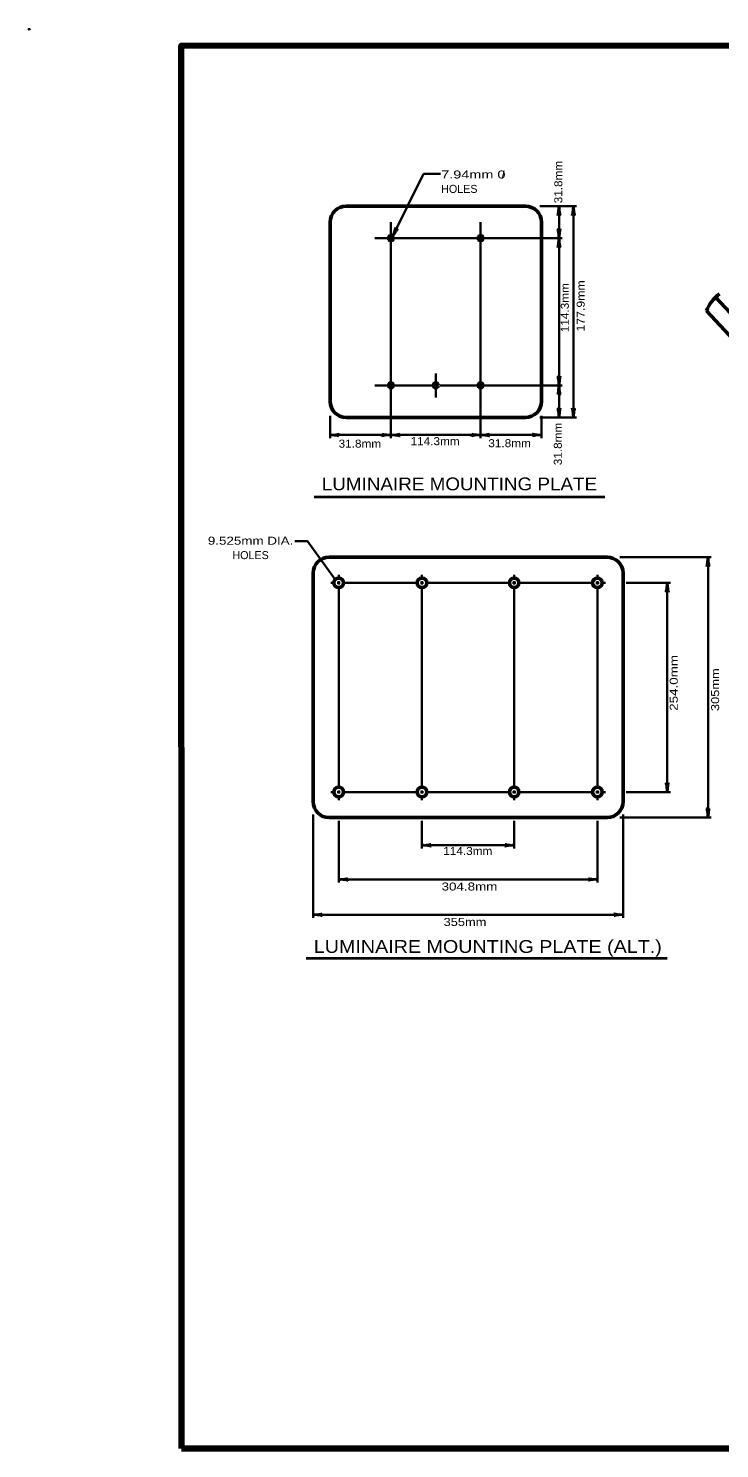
# Model space of a CAD drawing. Extents: x -94 to 619, y -64 to 390.
# Drawn here: x -94.2 to 121.7, y -53.9 to 389.8 of the extents above; entities that cross this region are included whole.
import ezdxf
from ezdxf.enums import TextEntityAlignment as Align

# ---------------------------------------------------------------- set-up
doc = ezdxf.new("R2010")
doc.units = 0
doc.header["$PDMODE"] = 32
doc.header["$PDSIZE"] = 0.5
doc.layers.add('1', color=7, linetype='Continuous', lineweight=13)

msp = doc.modelspace()

# ---------------------------------------------------------------- linework, layer by layer
at = {"layer": '1', "lineweight": 53}
for p, q in [((5.052, 334.27), (61.052, 334.27)), ((0.052, 273.27), (0.052, 329.27)), ((66.052, 329.27), (66.052, 273.27)), ((152.635, 271.333), (120.47, 305.825)), ((131.907, 286.229), (117.606, 301.565)), ((61.052, 268.27), (5.052, 268.27)), ((-0.255, 224.583), (86.543, 224.583)), ((-5.255, 148.221), (-5.255, 219.583)), ((91.543, 219.583), (91.543, 148.221)), ((86.543, 143.221), (-0.255, 143.221))]:
    msp.add_line(p, q, dxfattribs=at)
at = {"layer": '1', "lineweight": 35}
for p, q in [((65.552, 334.27), (77.052, 334.27)), ((71.552, 324.27), (71.552, 334.27)), ((76.052, 334.27), (76.052, 268.27)), ((19.052, 325.52), (19.052, 329.27)), ((47.052, 329.27), (47.052, 325.52)), ((14.052, 324.27), (17.802, 324.27)), ((18.802, 324.27), (19.302, 324.27)), ((19.052, 324.02), (19.052, 324.52)), ((20.302, 324.27), (45.802, 324.27)), ((46.802, 324.27), (47.302, 324.27)), ((47.052, 324.52), (47.052, 324.02)), ((48.302, 324.27), (72.552, 324.27)), ((71.552, 324.27), (71.552, 278.27)), ((19.052, 279.52), (19.052, 323.02)), ((47.052, 323.02), (47.052, 279.52)), ((33.052, 282.02), (33.052, 279.52)), ((17.802, 278.27), (14.052, 278.27)), ((19.302, 278.27), (18.802, 278.27)), ((19.052, 278.02), (19.052, 278.52)), ((19.052, 261.77), (19.052, 277.02)), ((31.802, 278.27), (20.302, 278.27)), ((33.302, 278.27), (32.802, 278.27)), ((33.052, 278.52), (33.052, 278.02)), ((33.052, 277.02), (33.052, 274.52)), ((45.802, 278.27), (34.302, 278.27)), ((47.302, 278.27), (46.802, 278.27)), ((47.052, 278.52), (47.052, 278.02)), ((47.052, 277.02), (47.052, 261.77)), ((72.552, 278.27), (48.302, 278.27)), ((71.552, 278.27), (71.552, 268.27)), ((0.052, 268.77), (0.052, 261.77)), ((65.552, 268.27), (77.052, 268.27)), ((66.052, 268.77), (66.052, 261.77)), ((19.052, 262.77), (0.052, 262.77)), ((-7.042, 229.638), (-10.927, 229.638)), ((1.684, 217.643), (-7.042, 229.638)), ((90.543, 224.583), (119.085, 224.583)), ((118.085, 224.583), (118.085, 143.221)), ((2.745, 217.583), (2.745, 219.083)), ((28.745, 217.583), (28.745, 219.083)), ((57.543, 217.583), (57.543, 219.083)), ((83.543, 217.583), (83.543, 219.083)), ((1.745, 216.583), (0.245, 216.583)), ((2.245, 216.583), (3.245, 216.583)), ((2.745, 216.083), (2.745, 217.083)), ((2.745, 152.221), (2.745, 215.583)), ((3.745, 216.583), (27.745, 216.583)), ((28.245, 216.583), (29.245, 216.583)), ((28.745, 217.083), (28.745, 216.083)), ((28.745, 215.583), (28.745, 152.221)), ((29.745, 216.583), (56.543, 216.583)), ((57.043, 216.583), (58.043, 216.583)), ((57.543, 217.083), (57.543, 216.083)), ((57.543, 215.583), (57.543, 152.221)), ((58.543, 216.583), (82.543, 216.583)), ((83.043, 216.583), (84.043, 216.583)), ((83.543, 217.083), (83.543, 216.083)), ((83.543, 215.583), (83.543, 152.221)), ((84.543, 216.583), (86.043, 216.583)), ((92.543, 216.583), (106.344, 216.583)), ((105.344, 216.583), (105.344, 151.221)), ((1.745, 151.221), (0.245, 151.221)), ((3.245, 151.221), (2.245, 151.221)), ((2.745, 150.721), (2.745, 151.721)), ((27.745, 151.221), (3.745, 151.221)), ((29.245, 151.221), (28.245, 151.221)), ((28.745, 151.721), (28.745, 150.721)), ((56.543, 151.221), (29.745, 151.221)), ((58.043, 151.221), (57.043, 151.221)), ((57.543, 151.721), (57.543, 150.721)), ((82.543, 151.221), (58.543, 151.221)), ((84.043, 151.221), (83.043, 151.221)), ((83.543, 151.721), (83.543, 150.721)), ((84.543, 151.221), (86.043, 151.221)), ((92.543, 151.221), (106.344, 151.221)), ((2.745, 150.221), (2.745, 148.721)), ((28.745, 150.221), (28.745, 148.721)), ((57.543, 150.221), (57.543, 148.721)), ((83.543, 150.221), (83.543, 148.721)), ((-5.255, 144.221), (-5.255, 111.869)), ((2.745, 142.221), (2.745, 122.9)), ((28.745, 142.221), (28.745, 133.588)), ((57.543, 142.221), (57.543, 133.588)), ((83.543, 142.221), (83.543, 122.9)), ((90.543, 143.221), (119.085, 143.221)), ((91.543, 144.221), (91.543, 111.869)), ((28.745, 134.588), (57.543, 134.588)), ((2.745, 123.9), (83.543, 123.9)), ((-5.255, 112.869), (91.543, 112.869))]:
    msp.add_line(p, q, dxfattribs=at)
at = {"layer": '1', "lineweight": 40}
for p, q in [((-4.929, 243.433), (85.864, 243.433)), ((-7.429, 99.306), (105.358, 99.306))]:
    msp.add_line(p, q, dxfattribs=at)
at = {"layer": '1', "lineweight": 158}
msp.add_line((613.334, -53.936), (-46.333, -53.936), dxfattribs=at)
msp.add_lwpolyline([(613.334, 384.481), (-46.416, 384.397), (-46.333, -53.936)], dxfattribs=at)
at = {"layer": '1', "lineweight": 35}
for points in [[(19.582, 324.8), (29.235, 344.332), (34.544, 344.332)], [(19.052, 262.77), (47.052, 262.77), (66.052, 262.77)]]:
    msp.add_lwpolyline(points, dxfattribs=at)
at = {"layer": '1', "lineweight": 53}
for centre, radius in [((19.052, 324.27), 0.75), ((47.052, 324.27), 0.75), ((19.052, 278.27), 0.75), ((33.052, 278.27), 0.75), ((47.052, 278.27), 0.75), ((2.745, 216.583), 1.5), ((28.745, 216.583), 1.5), ((57.543, 216.583), 1.5), ((83.543, 216.583), 1.5), ((2.745, 151.221), 1.5), ((28.745, 151.221), 1.5), ((57.543, 151.221), 1.5), ((83.543, 151.221), 1.5)]:
    msp.add_circle(centre, radius, dxfattribs=at)
for centre, radius, start, end in [((5.052, 329.27), 5, 90, 180), ((61.052, 329.27), 5, 0, 90), ((128.914, 297.056), 12.174, 126.36545, 158.25906), ((5.052, 273.27), 5, 180, 270), ((61.052, 273.27), 5, 270, 0), ((-0.255, 219.583), 5, 90, 180), ((86.543, 219.583), 5, 0, 90), ((-0.255, 148.221), 5, 180, 270), ((86.543, 148.221), 5, 270, 0)]:
    msp.add_arc(centre, radius, start, end, dxfattribs=at)
at = {"layer": '1', "lineweight": 40}
for centre, major_axis, ratio, start_param, end_param in [((71.34, 333.149), (0.176, 1.756), 0.07063, 3.1407148, 5.41811), ((71.34, 333.149), (0.176, 1.756), 0.07063, 3.1407148, 5.41811), ((71.828, 333.179), (-0.156, 1.786), 0.122415, 0.8963533, 3.1415927), ((71.828, 333.179), (-0.156, 1.786), 0.122415, 0.8963533, 3.1415927), ((75.84, 333.149), (0.176, 1.756), 0.07063, 3.1407148, 5.41811), ((75.84, 333.149), (0.176, 1.756), 0.07063, 3.1407148, 5.41811), ((76.328, 333.179), (-0.156, 1.786), 0.122415, 0.8963533, 3.1415927), ((76.328, 333.179), (-0.156, 1.786), 0.122415, 0.8963533, 3.1415927), ((19.818, 325.901), (-0.651, -1.67), 0.122415, 0.8963533, 3.1415927), ((20.268, 325.711), (0.936, 1.497), 0.07063, 6.2823074, 8.5597026), ((71.276, 325.361), (0.156, -1.786), 0.122415, 0.8963533, 3.1415927), ((71.276, 325.361), (0.156, -1.786), 0.122415, 0.8963533, 3.1415927), ((71.34, 323.149), (0.176, 1.756), 0.07063, 3.1407148, 5.41811), ((71.34, 323.149), (0.176, 1.756), 0.07063, 3.1407148, 5.41811), ((71.828, 323.179), (-0.156, 1.786), 0.122415, 0.8963533, 3.1415927), ((71.828, 323.179), (-0.156, 1.786), 0.122415, 0.8963533, 3.1415927), ((71.763, 325.39), (-0.176, -1.756), 0.07063, 3.1407148, 5.41811), ((71.763, 325.39), (-0.176, -1.756), 0.07063, 3.1407148, 5.41811), ((71.276, 279.361), (0.156, -1.786), 0.122415, 0.8963533, 3.1415927), ((71.276, 279.361), (0.156, -1.786), 0.122415, 0.8963533, 3.1415927), ((71.763, 279.39), (-0.176, -1.756), 0.07063, 3.1407148, 5.41811), ((71.763, 279.39), (-0.176, -1.756), 0.07063, 3.1407148, 5.41811), ((71.34, 277.149), (0.176, 1.756), 0.07063, 3.1407148, 5.41811), ((71.34, 277.149), (0.176, 1.756), 0.07063, 3.1407148, 5.41811), ((71.828, 277.179), (-0.156, 1.786), 0.122415, 0.8963533, 3.1415927), ((71.828, 277.179), (-0.156, 1.786), 0.122415, 0.8963533, 3.1415927), ((71.276, 269.361), (0.156, -1.786), 0.122415, 0.8963533, 3.1415927), ((71.276, 269.361), (0.156, -1.786), 0.122415, 0.8963533, 3.1415927), ((71.763, 269.39), (-0.176, -1.756), 0.07063, 3.1407148, 5.41811), ((71.763, 269.39), (-0.176, -1.756), 0.07063, 3.1407148, 5.41811), ((75.776, 269.361), (0.156, -1.786), 0.122415, 0.8963533, 3.1415927), ((75.776, 269.361), (0.156, -1.786), 0.122415, 0.8963533, 3.1415927), ((76.263, 269.39), (-0.176, -1.756), 0.07063, 3.1407148, 5.41811), ((76.263, 269.39), (-0.176, -1.756), 0.07063, 3.1407148, 5.41811), ((1.172, 262.558), (-1.756, 0.176), 0.07063, 3.1407148, 5.41811), ((1.143, 263.046), (-1.786, -0.156), 0.122415, 0.8963533, 3.1415927), ((17.961, 262.494), (1.786, 0.156), 0.122415, 0.8963533, 3.1415927), ((17.961, 262.494), (1.786, 0.156), 0.122415, 0.8963533, 3.1415927), ((17.931, 262.981), (1.756, -0.176), 0.07063, 3.1407148, 5.41811), ((17.931, 262.981), (1.756, -0.176), 0.07063, 3.1407148, 5.41811), ((20.172, 262.558), (-1.756, 0.176), 0.07063, 3.1407148, 5.41811), ((20.172, 262.558), (-1.756, 0.176), 0.07063, 3.1407148, 5.41811), ((20.143, 263.046), (-1.786, -0.156), 0.122415, 0.8963533, 3.1415927), ((20.143, 263.046), (-1.786, -0.156), 0.122415, 0.8963533, 3.1415927), ((45.961, 262.494), (1.786, 0.156), 0.122415, 0.8963533, 3.1415927), ((45.961, 262.494), (1.786, 0.156), 0.122415, 0.8963533, 3.1415927), ((45.931, 262.981), (1.756, -0.176), 0.07063, 3.1407148, 5.41811), ((45.931, 262.981), (1.756, -0.176), 0.07063, 3.1407148, 5.41811), ((48.172, 262.558), (-1.756, 0.176), 0.07063, 3.1407148, 5.41811), ((48.172, 262.558), (-1.756, 0.176), 0.07063, 3.1407148, 5.41811), ((48.143, 263.046), (-1.786, -0.156), 0.122415, 0.8963533, 3.1415927), ((48.143, 263.046), (-1.786, -0.156), 0.122415, 0.8963533, 3.1415927), ((64.961, 262.494), (1.786, 0.156), 0.122415, 0.8963533, 3.1415927), ((64.961, 262.494), (1.786, 0.156), 0.122415, 0.8963533, 3.1415927), ((64.931, 262.981), (1.756, -0.176), 0.07063, 3.1407148, 5.41811), ((64.931, 262.981), (1.756, -0.176), 0.07063, 3.1407148, 5.41811), ((117.873, 223.462), (0.176, 1.756), 0.07063, 3.1407148, 5.41811), ((117.873, 223.462), (0.176, 1.756), 0.07063, 3.1407148, 5.41811), ((118.361, 223.491), (-0.156, 1.786), 0.122415, 0.8963533, 3.1415927), ((118.361, 223.491), (-0.156, 1.786), 0.122415, 0.8963533, 3.1415927), ((105.132, 215.462), (0.176, 1.756), 0.07063, 3.1407148, 5.41811), ((105.132, 215.462), (0.176, 1.756), 0.07063, 3.1407148, 5.41811), ((105.62, 215.491), (-0.156, 1.786), 0.122415, 0.8963533, 3.1415927), ((105.62, 215.491), (-0.156, 1.786), 0.122415, 0.8963533, 3.1415927), ((105.068, 152.312), (0.156, -1.786), 0.122415, 0.8963533, 3.1415927), ((105.068, 152.312), (0.156, -1.786), 0.122415, 0.8963533, 3.1415927), ((105.556, 152.341), (-0.176, -1.756), 0.07063, 3.1407148, 5.41811), ((105.556, 152.341), (-0.176, -1.756), 0.07063, 3.1407148, 5.41811), ((117.808, 144.312), (0.156, -1.786), 0.122415, 0.8963533, 3.1415927), ((117.808, 144.312), (0.156, -1.786), 0.122415, 0.8963533, 3.1415927), ((118.296, 144.341), (-0.176, -1.756), 0.07063, 3.1407148, 5.41811), ((118.296, 144.341), (-0.176, -1.756), 0.07063, 3.1407148, 5.41811), ((29.865, 134.376), (-1.756, 0.176), 0.07063, 3.1407148, 5.41811), ((29.865, 134.376), (-1.756, 0.176), 0.07063, 3.1407148, 5.41811), ((29.836, 134.864), (-1.786, -0.156), 0.122415, 0.8963533, 3.1415927), ((29.836, 134.864), (-1.786, -0.156), 0.122415, 0.8963533, 3.1415927), ((56.452, 134.312), (1.786, 0.156), 0.122415, 0.8963533, 3.1415927), ((56.452, 134.312), (1.786, 0.156), 0.122415, 0.8963533, 3.1415927), ((56.422, 134.8), (1.756, -0.176), 0.07063, 3.1407148, 5.41811), ((56.422, 134.8), (1.756, -0.176), 0.07063, 3.1407148, 5.41811), ((3.836, 124.176), (-1.786, -0.156), 0.122415, 0.8963533, 3.1415927), ((3.836, 124.176), (-1.786, -0.156), 0.122415, 0.8963533, 3.1415927), ((82.422, 124.111), (1.756, -0.176), 0.07063, 3.1407148, 5.41811), ((82.422, 124.111), (1.756, -0.176), 0.07063, 3.1407148, 5.41811), ((3.865, 123.688), (-1.756, 0.176), 0.07063, 3.1407148, 5.41811), ((3.865, 123.688), (-1.756, 0.176), 0.07063, 3.1407148, 5.41811), ((82.452, 123.623), (1.786, 0.156), 0.122415, 0.8963533, 3.1415927), ((82.452, 123.623), (1.786, 0.156), 0.122415, 0.8963533, 3.1415927), ((-4.135, 112.657), (-1.756, 0.176), 0.07063, 3.1407148, 5.41811), ((-4.135, 112.657), (-1.756, 0.176), 0.07063, 3.1407148, 5.41811), ((-4.135, 112.657), (-1.756, 0.176), 0.07063, 3.1407148, 5.41811), ((-4.164, 113.145), (-1.786, -0.156), 0.122415, 0.8963533, 3.1415927), ((-4.164, 113.145), (-1.786, -0.156), 0.122415, 0.8963533, 3.1415927), ((-4.164, 113.145), (-1.786, -0.156), 0.122415, 0.8963533, 3.1415927), ((90.452, 112.593), (1.786, 0.156), 0.122415, 0.8963533, 3.1415927), ((90.452, 112.593), (1.786, 0.156), 0.122415, 0.8963533, 3.1415927), ((90.422, 113.08), (1.756, -0.176), 0.07063, 3.1407148, 5.41811), ((90.422, 113.08), (1.756, -0.176), 0.07063, 3.1407148, 5.41811)]:
    msp.add_ellipse(centre, major_axis=major_axis, ratio=ratio, start_param=start_param, end_param=end_param, dxfattribs=at)
at = {"layer": '1'}
msp.add_point((-93.916, 389.564), dxfattribs=at)

# ---------------------------------------------------------------- texts
for s, width, p in [('31.8mm', 1.1, (72.57, 335.155)), ('177.9mm', 1.15, (79.567, 295.08)), ('114.3mm', 1.1, (74.601, 294.887)), ('31.8mm', 1.1, (72.422, 253.311)), ('254.0mm', 1.25, (108.626, 176.598)), ('305mm', 1.2, (121.557, 176.508))]:
    msp.add_text(s, height=2.5, rotation=90, dxfattribs=dict(at, width=width)).set_placement(p)
for s, height, width, p in [('7.94mm 0', 2.5, 1.35, (34.75, 342.916)), ('114.3mm', 2.5, 1.1, (25.186, 259.593)), ('31.8mm', 2.5, 1.1, (2.708, 258.813)), ('31.8mm', 2.5, 1.1, (49.465, 258.961)), ('LUMINAIRE MOUNTING PLATE', 4, 1.1, (-2.532, 245.489)), ('114.3mm', 2.5, 1.1, (35.386, 131.553)), ('304.8mm', 2.5, 1.25, (34.874, 120.442)), ('355mm', 2.5, 1.2, (35.493, 109.364)), ('LUMINAIRE MOUNTING PLATE (ALT.)', 4, 1.15, (-5.032, 100.95))]:
    msp.add_text(s, height=height, dxfattribs=dict(at, width=width)).set_placement(p)
for s, p in [('/', (53.618, 342.869)), ('HOLES', (34.75, 338.416))]:
    msp.add_text(s, height=2.5, dxfattribs=at).set_placement(p)
at = {"layer": '1', "width": 1.25}
msp.add_text('9.525mm DIA.', height=2.5, dxfattribs=at).set_placement((-24.778, 228.487), align=Align.CENTER)
at = {"layer": '1'}
msp.add_text('HOLES', height=2.5, dxfattribs=at).set_placement((-24.778, 223.987), align=Align.CENTER)

doc.saveas('drawing.dxf')
